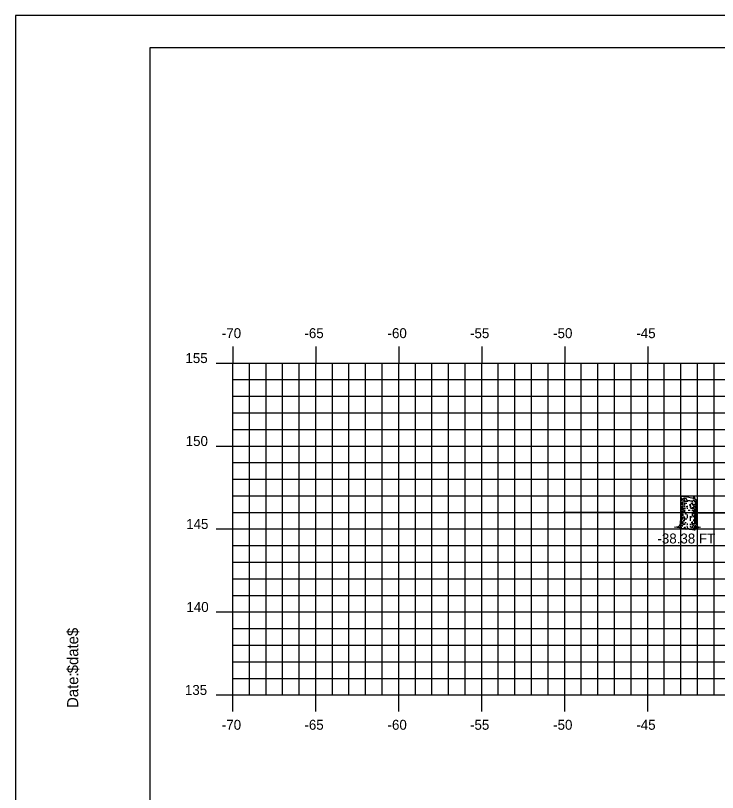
# Model space of a CAD drawing. Extents: x 1146746 to 1146916, y 608981 to 609091.
# Drawn here: x 1146746.33 to 1146788.63, y 609044.46 to 609091.28 of the extents above; entities that cross this region are included whole.
import ezdxf

# ---------------------------------------------------------------- set-up
doc = ezdxf.new("R2010")
doc.units = 0
for name, color, linetype in [('BORDER', 7, 'Continuous'), ('D_Text_Standard', 7, 'Continuous'), ('H_V ANNOTATION', 7, 'Continuous'), ('MAJOR', 7, 'Continuous'), ('MINOR', 7, 'Continuous'), ('PLOT BOUNDARY', 7, 'Continuous'), ('S_Roadway_Centerline', 7, 'Continuous'), ('S_Trees_Decid_NonPay', 7, 'Continuous')]:
    doc.layers.add(name, color=color, linetype=linetype)

msp = doc.modelspace()

# ---------------------------------------------------------------- linework, layer by layer
at = {"layer": 'BORDER'}
msp.add_lwpolyline([(1146754.428, 608984.335), (1146914.428, 608984.335), (1146914.428, 609089.335), (1146754.428, 609089.335)], close=True, dxfattribs=at)
at = {"layer": 'MAJOR'}
for p, q in [((1146759.428, 609071.337), (1146759.428, 609070.335)), ((1146764.428, 609071.337), (1146764.428, 609070.335)), ((1146769.428, 609071.337), (1146769.428, 609070.335)), ((1146774.428, 609071.337), (1146774.428, 609070.335)), ((1146779.428, 609071.337), (1146779.428, 609070.335)), ((1146784.428, 609071.337), (1146784.428, 609070.335)), ((1146758.426, 609070.335), (1146759.428, 609070.335)), ((1146759.428, 609070.335), (1146899.428, 609070.335)), ((1146759.428, 609050.335), (1146759.428, 609070.335)), ((1146759.428, 609050.335), (1146759.428, 609070.335)), ((1146759.428, 609070.335), (1146899.428, 609070.335)), ((1146764.428, 609050.335), (1146764.428, 609070.335)), ((1146769.428, 609050.335), (1146769.428, 609070.335)), ((1146774.428, 609050.335), (1146774.428, 609070.335)), ((1146779.428, 609050.335), (1146779.428, 609070.335)), ((1146784.428, 609050.335), (1146784.428, 609070.335)), ((1146758.426, 609065.335), (1146759.428, 609065.335)), ((1146759.428, 609065.335), (1146899.428, 609065.335)), ((1146758.426, 609060.335), (1146759.428, 609060.335)), ((1146759.428, 609060.335), (1146899.428, 609060.335)), ((1146758.426, 609055.335), (1146759.428, 609055.335)), ((1146759.428, 609055.335), (1146899.428, 609055.335)), ((1146758.426, 609050.335), (1146759.428, 609050.335)), ((1146759.428, 609050.335), (1146899.428, 609050.335)), ((1146759.428, 609050.335), (1146899.428, 609050.335)), ((1146759.428, 609049.333), (1146759.428, 609050.335)), ((1146764.428, 609049.333), (1146764.428, 609050.335)), ((1146769.428, 609049.333), (1146769.428, 609050.335)), ((1146774.428, 609049.333), (1146774.428, 609050.335)), ((1146779.428, 609049.333), (1146779.428, 609050.335)), ((1146784.428, 609049.333), (1146784.428, 609050.335))]:
    msp.add_line(p, q, dxfattribs=at)
at = {"layer": 'MINOR'}
for p, q in [((1146760.428, 609050.335), (1146760.428, 609070.335)), ((1146761.428, 609050.335), (1146761.428, 609070.335)), ((1146762.428, 609050.335), (1146762.428, 609070.335)), ((1146763.428, 609050.335), (1146763.428, 609070.335)), ((1146765.428, 609050.335), (1146765.428, 609070.335)), ((1146766.428, 609050.335), (1146766.428, 609070.335)), ((1146767.428, 609050.335), (1146767.428, 609070.335)), ((1146768.428, 609050.335), (1146768.428, 609070.335)), ((1146770.428, 609050.335), (1146770.428, 609070.335)), ((1146771.428, 609050.335), (1146771.428, 609070.335)), ((1146772.428, 609050.335), (1146772.428, 609070.335)), ((1146773.428, 609050.335), (1146773.428, 609070.335)), ((1146775.428, 609050.335), (1146775.428, 609070.335)), ((1146776.428, 609050.335), (1146776.428, 609070.335)), ((1146777.428, 609050.335), (1146777.428, 609070.335)), ((1146778.428, 609050.335), (1146778.428, 609070.335)), ((1146780.428, 609050.335), (1146780.428, 609070.335)), ((1146781.428, 609050.335), (1146781.428, 609070.335)), ((1146782.428, 609050.335), (1146782.428, 609070.335)), ((1146783.428, 609050.335), (1146783.428, 609070.335)), ((1146785.428, 609050.335), (1146785.428, 609070.335)), ((1146786.428, 609050.335), (1146786.428, 609070.335)), ((1146787.428, 609050.335), (1146787.428, 609070.335)), ((1146788.428, 609050.335), (1146788.428, 609070.335)), ((1146759.428, 609069.335), (1146899.428, 609069.335)), ((1146759.428, 609069.335), (1146760.43, 609069.335)), ((1146759.428, 609068.335), (1146899.428, 609068.335)), ((1146759.428, 609068.335), (1146760.43, 609068.335)), ((1146759.428, 609067.335), (1146899.428, 609067.335)), ((1146759.428, 609067.335), (1146760.43, 609067.335)), ((1146759.428, 609066.335), (1146899.428, 609066.335)), ((1146759.428, 609066.335), (1146760.43, 609066.335)), ((1146759.428, 609064.335), (1146899.428, 609064.335)), ((1146759.428, 609064.335), (1146760.43, 609064.335)), ((1146759.428, 609063.335), (1146899.428, 609063.335)), ((1146759.428, 609063.335), (1146760.43, 609063.335)), ((1146759.428, 609062.335), (1146899.428, 609062.335)), ((1146759.428, 609062.335), (1146760.43, 609062.335)), ((1146759.428, 609061.335), (1146899.428, 609061.335)), ((1146759.428, 609061.335), (1146760.43, 609061.335)), ((1146759.428, 609059.335), (1146899.428, 609059.335)), ((1146759.428, 609059.335), (1146760.43, 609059.335)), ((1146759.428, 609058.335), (1146899.428, 609058.335)), ((1146759.428, 609058.335), (1146760.43, 609058.335)), ((1146759.428, 609057.335), (1146899.428, 609057.335)), ((1146759.428, 609057.335), (1146760.43, 609057.335)), ((1146759.428, 609056.335), (1146899.428, 609056.335)), ((1146759.428, 609056.335), (1146760.43, 609056.335)), ((1146759.428, 609054.335), (1146899.428, 609054.335)), ((1146759.428, 609054.335), (1146760.43, 609054.335)), ((1146759.428, 609053.335), (1146899.428, 609053.335)), ((1146759.428, 609053.335), (1146760.43, 609053.335)), ((1146759.428, 609052.335), (1146899.428, 609052.335)), ((1146759.428, 609052.335), (1146760.43, 609052.335)), ((1146759.428, 609051.335), (1146899.428, 609051.335)), ((1146759.428, 609051.335), (1146760.43, 609051.335))]:
    msp.add_line(p, q, dxfattribs=at)
at = {"layer": 'PLOT BOUNDARY'}
msp.add_lwpolyline([(1146746.335, 608981.276), (1146916.335, 608981.276), (1146916.335, 609091.276), (1146746.335, 609091.276)], close=True, dxfattribs=at)
at = {"layer": 'S_Roadway_Centerline'}
msp.add_lwpolyline([(1146779.336, 609061.362), (1146783.547, 609061.347), (1146805.256, 609061.134), (1146809.082, 609059.861), (1146811.069, 609059.254), (1146812.495, 609059.513), (1146815.447, 609060.131), (1146817.252, 609060.222), (1146817.72, 609060.231), (1146827.705, 609060.397), (1146828.534, 609060.409), (1146838.673, 609060.265), (1146839.449, 609060.245), (1146840.103, 609060.192), (1146841.398, 609060.074), (1146844.953, 609059.719), (1146845.827, 609059.059), (1146847.055, 609058.398), (1146848.196, 609058.671), (1146848.525, 609058.74), (1146851.732, 609059.665), (1146855.862, 609060.73), (1146861.215, 609060.999), (1146871.652, 609060.902)], dxfattribs=at)
at = {"layer": 'S_Trees_Decid_NonPay'}
for p, q in [((1146786.469, 609062.189), (1146786.469, 609062.095)), ((1146786.469, 609061.868), (1146786.469, 609061.786)), ((1146786.537, 609062.103), (1146786.537, 609061.802)), ((1146786.537, 609061.773), (1146786.537, 609061.642)), ((1146786.656, 609062.12), (1146786.656, 609061.971)), ((1146786.656, 609061.923), (1146786.656, 609061.755)), ((1146786.803, 609062.074), (1146786.803, 609061.967)), ((1146786.803, 609061.738), (1146786.803, 609061.652)), ((1146786.983, 609061.838), (1146786.983, 609061.637)), ((1146787.1, 609062.021), (1146787.1, 609061.943)), ((1146787.1, 609061.856), (1146787.1, 609061.771)), ((1146787.187, 609061.838), (1146787.187, 609061.751)), ((1146787.258, 609062.011), (1146787.258, 609061.959)), ((1146787.258, 609061.856), (1146787.258, 609061.773)), ((1146787.258, 609061.738), (1146787.258, 609061.664)), ((1146787.3, 609062.016), (1146787.3, 609061.798)), ((1146787.3, 609061.729), (1146787.3, 609061.578)), ((1146787.327, 609061.946), (1146787.327, 609061.864)), ((1146787.327, 609061.794), (1146787.327, 609061.664)), ((1146786.469, 609061.716), (1146786.469, 609061.465)), ((1146786.469, 609061.382), (1146786.469, 609061.152)), ((1146786.537, 609061.608), (1146786.537, 609061.327)), ((1146786.537, 609061.257), (1146786.537, 609061.112)), ((1146786.656, 609061.448), (1146786.656, 609061.3)), ((1146786.803, 609061.617), (1146786.803, 609061.547)), ((1146787.1, 609061.66), (1146787.1, 609061.559)), ((1146787.1, 609061.475), (1146787.1, 609061.399)), ((1146787.187, 609061.681), (1146787.187, 609061.559)), ((1146787.187, 609061.484), (1146787.187, 609061.37)), ((1146787.187, 609061.308), (1146787.187, 609061.226)), ((1146787.258, 609061.637), (1146787.258, 609061.578)), ((1146787.258, 609061.525), (1146787.258, 609061.343)), ((1146787.258, 609061.312), (1146787.258, 609061.23)), ((1146787.3, 609061.473), (1146787.3, 609061.395)), ((1146787.3, 609061.368), (1146787.3, 609061.261)), ((1146787.327, 609061.642), (1146787.327, 609061.46)), ((1146787.327, 609061.413), (1146787.327, 609061.166)), ((1146786.469, 609061.082), (1146786.469, 609060.921)), ((1146786.469, 609060.904), (1146786.469, 609060.799)), ((1146786.537, 609061.042), (1146786.537, 609060.901)), ((1146786.537, 609060.799), (1146786.537, 609060.618)), ((1146786.656, 609061.03), (1146786.656, 609060.878)), ((1146786.803, 609061.214), (1146786.803, 609060.991)), ((1146786.983, 609061.1), (1146786.983, 609060.913)), ((1146786.983, 609060.882), (1146786.983, 609060.829)), ((1146787.1, 609061.214), (1146787.1, 609061.116)), ((1146787.1, 609060.792), (1146787.1, 609060.567)), ((1146787.187, 609061.139), (1146787.187, 609061.042)), ((1146787.187, 609060.913), (1146787.187, 609060.814)), ((1146787.258, 609061.176), (1146787.258, 609061.006)), ((1146787.258, 609060.972), (1146787.258, 609060.693)), ((1146787.3, 609061.226), (1146787.3, 609061.125)), ((1146787.3, 609061.099), (1146787.3, 609060.917)), ((1146787.3, 609060.814), (1146787.3, 609060.622)), ((1146787.327, 609061.147), (1146787.327, 609061.053)), ((1146787.329, 609061), (1146787.328, 609060.74)), ((1146786.469, 609060.763), (1146786.469, 609060.639)), ((1146786.536, 609060.559), (1146786.495, 609060.462)), ((1146786.656, 609060.666), (1146786.656, 609060.588)), ((1146786.803, 609060.658), (1146786.803, 609060.591)), ((1146786.843, 609060.372), (1146786.808, 609060.517)), ((1146786.983, 609060.653), (1146786.983, 609060.563)), ((1146787.187, 609060.685), (1146787.187, 609060.626)), ((1146787.258, 609060.64), (1146787.258, 609060.614)), ((1146787.298, 609060.575), (1146787.333, 609060.524)), ((1146787.38, 609060.454), (1146787.313, 609060.485)), ((1146787.327, 609060.701), (1146787.327, 609060.627))]:
    msp.add_line(p, q, dxfattribs=at)
for points in [[(1146787.368, 609062.053), (1146787.368, 609060.641), (1146787.391, 609060.493), (1146787.594, 609060.45), (1146787.454, 609060.414), (1146787.236, 609060.396), (1146787.166, 609060.353), (1146787.288, 609060.264), (1146786.956, 609060.307), (1146786.843, 609060.372), (1146786.75, 609060.311), (1146786.695, 609060.39), (1146786.703, 609060.427), (1146786.641, 609060.429), (1146786.59, 609060.372), (1146786.357, 609060.32), (1146786.485, 609060.408), (1146786.353, 609060.41), (1146786.044, 609060.448), (1146786.283, 609060.479), (1146786.361, 609060.536), (1146786.4, 609060.658), (1146786.417, 609061.011), (1146786.417, 609062.245)], [(1146786.781, 609062.079), (1146786.773, 609062.146), (1146786.748, 609062.151), (1146786.74, 609062.185), (1146786.709, 609062.171), (1146786.695, 609062.185), (1146786.67, 609062.162), (1146786.647, 609062.171), (1146786.635, 609062.22), (1146786.627, 609062.177), (1146786.596, 609062.185), (1146786.593, 609062.134)], [(1146787.273, 609062.134), (1146787.269, 609062.229), (1146787.255, 609062.202), (1146787.255, 609062.323), (1146787.234, 609062.259), (1146787.22, 609062.292), (1146787.203, 609062.236), (1146787.187, 609062.254), (1146787.168, 609062.245), (1146787.149, 609062.178)], [(1146787.251, 609062.01), (1146787.234, 609062.072), (1146787.212, 609062.06), (1146787.181, 609062.095), (1146787.147, 609062.017)], [(1146786.466, 609060.596), (1146786.458, 609060.519), (1146786.38, 609060.47)], [(1146786.991, 609060.513), (1146786.991, 609060.477), (1146787.042, 609060.446), (1146787.059, 609060.396)], [(1146787.103, 609060.519), (1146787.109, 609060.45), (1146787.172, 609060.437)], [(1146787.25, 609060.485), (1146787.207, 609060.519), (1146787.199, 609060.567)], [(1146787.329, 609060.501), (1146787.25, 609060.485), (1146787.234, 609060.441)]]:
    msp.add_lwpolyline(points, dxfattribs=at)
for centre, radius, start, end in [((1146786.435, 609062.245), 0.0179, 168.1723, 184.2278), ((1146786.441, 609062.246), 0.0237, 184.2278, 198.1723), ((1146786.435, 609062.245), 0.0179, 152.1168, 168.1723), ((1146786.45, 609062.249), 0.0336, 198.1723, 216.9486), ((1146786.44, 609062.242), 0.0237, 138.1723, 152.1168), ((1146786.448, 609062.236), 0.0336, 119.396, 138.1723), ((1146786.498, 609062.285), 0.0935, 216.9486, 228.1723), ((1146786.477, 609062.184), 0.0935, 108.1723, 119.396), ((1146786.651, 609062.455), 0.322, 228.1723, 250.2902), ((1146786.548, 609061.967), 0.322, 86.0543, 108.1723), ((1146786.398, 609059.787), 2.507, 78.1723, 86.0543), ((1146786.398, 609059.787), 2.507, 70.2902, 78.1723), ((1146786.436, 609062.098), 0.0191, 163.9485, 180), ((1146786.436, 609062.098), 0.0191, 180, 196.0515), ((1146786.442, 609062.099), 0.0252, 196.0515, 210), ((1146786.436, 609061.884), 0.0191, 163.9485, 180), ((1146786.436, 609061.884), 0.0191, 180, 196.0515), ((1146786.442, 609061.885), 0.0252, 196.0515, 210), ((1146786.436, 609061.781), 0.0191, 163.9485, 180), ((1146786.436, 609061.781), 0.0191, 180, 196.0515), ((1146786.442, 609061.782), 0.0252, 196.0515, 210), ((1146786.451, 609062.105), 0.0356, 210, 228.7494), ((1146786.451, 609061.89), 0.0356, 210, 228.7494), ((1146786.451, 609061.788), 0.0356, 210, 228.7494), ((1146786.492, 609062.152), 0.0984, 228.7494, 240), ((1146786.492, 609061.938), 0.0984, 228.7494, 240), ((1146786.492, 609061.835), 0.0984, 228.7494, 240), ((1146786.606, 609062.349), 0.326, 240, 248.3243), ((1146786.606, 609062.135), 0.326, 240, 243.5719), ((1146786.606, 609062.032), 0.326, 240, 243.243), ((1146786.606, 609062.236), 0.326, 240.9099, 257.8036), ((1146786.606, 609062.135), 0.326, 250.4167, 261.8968), ((1146786.606, 609062.349), 0.326, 257.8036, 261.8968), ((1146787.388, 609064.512), 2.507, 250.2902, 251.5281), ((1146786.892, 609064.359), 2.356, 261.8968, 263.2799), ((1146786.892, 609064.145), 2.356, 261.8968, 262.5519), ((1146786.892, 609064.246), 2.356, 264.242, 267.3673), ((1146786.892, 609064.359), 2.356, 265.24, 267.8386), ((1146787.388, 609064.512), 2.507, 255.9987, 258.1723), ((1146787.388, 609064.512), 2.507, 258.1723, 264.5013), ((1146786.892, 609064.145), 2.356, 270.8119, 272.1981), ((1146786.892, 609064.246), 2.356, 273.1481, 276.7734), ((1146786.892, 609064.145), 2.356, 275.0647, 278.1032), ((1146787.178, 609062.135), 0.326, 278.1032, 279.0854), ((1146787.135, 609061.844), 0.322, 48.1723, 70.2902), ((1146787.237, 609062.332), 0.322, 272.4479, 288.1723), ((1146787.178, 609062.236), 0.326, 291.9506, 300), ((1146787.178, 609062.135), 0.326, 291.9506, 300), ((1146787.308, 609062.115), 0.0935, 288.1723, 299.396), ((1146787.292, 609062.039), 0.0984, 300, 311.2506), ((1146787.292, 609061.938), 0.0984, 300, 311.2506), ((1146787.287, 609062.014), 0.0935, 36.9486, 48.1723), ((1146787.338, 609062.063), 0.0336, 299.396, 318.1723), ((1146787.333, 609061.991), 0.0356, 311.2506, 330), ((1146787.333, 609061.89), 0.0356, 311.2506, 330), ((1146787.335, 609062.05), 0.0336, 18.1723, 36.9486), ((1146787.345, 609062.056), 0.0237, 318.1723, 332.1168), ((1146787.342, 609061.986), 0.0252, 330, 343.9485), ((1146787.342, 609061.885), 0.0252, 330, 343.9485), ((1146787.35, 609062.053), 0.0179, 332.1168, 348.1723), ((1146787.344, 609062.053), 0.0237, 4.2278, 18.1723), ((1146787.348, 609061.984), 0.0191, 360, 6.1128), ((1146787.348, 609061.984), 0.0191, 343.9485, 360), ((1146787.348, 609061.884), 0.0191, 360, 6.1128), ((1146787.348, 609061.884), 0.0191, 343.9485, 360), ((1146787.348, 609061.781), 0.0191, 360, 6.1128), ((1146787.348, 609061.781), 0.0191, 343.9485, 360), ((1146787.35, 609062.053), 0.0179, 348.1723, 4.2278), ((1146786.433, 609061.346), 0.0191, 163.9485, 180), ((1146786.436, 609061.561), 0.0191, 163.9485, 180), ((1146786.436, 609061.561), 0.0191, 180, 196.0515), ((1146786.442, 609061.562), 0.0252, 196.0515, 210), ((1146786.436, 609061.446), 0.0191, 163.9485, 180), ((1146786.436, 609061.446), 0.0191, 180, 196.0515), ((1146786.442, 609061.448), 0.0252, 196.0515, 210), ((1146786.451, 609061.567), 0.0356, 210, 228.7494), ((1146786.451, 609061.453), 0.0356, 210, 228.7494), ((1146786.492, 609061.615), 0.0984, 228.7494, 240), ((1146786.493, 609061.5), 0.0984, 228.7494, 240), ((1146786.603, 609061.597), 0.326, 240, 256.9079), ((1146786.606, 609061.812), 0.326, 240, 245.1545), ((1146786.607, 609061.697), 0.326, 240, 247.8656), ((1146786.606, 609061.927), 0.326, 245.1545, 257.8036), ((1146786.606, 609062.032), 0.326, 251.6831, 257.8036), ((1146786.607, 609061.697), 0.326, 257.6699, 261.8968), ((1146786.893, 609063.707), 2.356, 261.8968, 262.8615), ((1146786.892, 609063.822), 2.356, 262.6588, 264.7911), ((1146786.892, 609063.937), 2.356, 263.2682, 265.6362), ((1146786.892, 609064.042), 2.356, 263.3413, 264.9946), ((1146786.89, 609063.607), 2.356, 264.3443, 266.8529), ((1146786.892, 609064.042), 2.356, 266.5036, 267.8386), ((1146786.892, 609063.822), 2.356, 269.5578, 270), ((1146786.892, 609063.822), 2.356, 270, 272.414), ((1146786.892, 609064.042), 2.356, 272.1981, 273.9741), ((1146786.892, 609063.937), 2.356, 273.0067, 275.0647), ((1146786.89, 609063.607), 2.356, 274.9734, 277.2455), ((1146786.892, 609063.822), 2.356, 275.0647, 277.1868), ((1146786.892, 609063.937), 2.356, 277.1868, 278.1032), ((1146786.892, 609064.042), 2.356, 277.3838, 278.1032), ((1146787.178, 609062.032), 0.326, 278.1032, 284.0382), ((1146787.178, 609061.927), 0.326, 278.1032, 284.0382), ((1146787.178, 609061.812), 0.326, 284.0382, 300), ((1146787.179, 609061.697), 0.326, 283.9036, 291.8098), ((1146787.178, 609061.927), 0.326, 291.9506, 300), ((1146787.176, 609061.597), 0.326, 292.4049, 300), ((1146787.179, 609061.697), 0.326, 297.0058, 300), ((1146787.29, 609061.4), 0.0984, 300, 311.2506), ((1146787.292, 609061.73), 0.0984, 300, 311.2506), ((1146787.292, 609061.615), 0.0984, 300, 311.2506), ((1146787.293, 609061.5), 0.0984, 300, 311.2506), ((1146787.331, 609061.353), 0.0356, 311.2506, 330), ((1146787.333, 609061.683), 0.0356, 311.2506, 330), ((1146787.333, 609061.567), 0.0356, 311.2506, 330), ((1146787.334, 609061.453), 0.0356, 311.2506, 330), ((1146787.34, 609061.348), 0.0252, 330, 343.9485), ((1146787.342, 609061.677), 0.0252, 330, 343.9485), ((1146787.342, 609061.562), 0.0252, 330, 343.9485), ((1146787.346, 609061.346), 0.0191, 343.9485, 360), ((1146787.343, 609061.448), 0.0252, 330, 343.9485), ((1146787.346, 609061.346), 0.0191, 0, 6.1128), ((1146787.348, 609061.676), 0.0191, 360, 6.1128), ((1146787.348, 609061.676), 0.0191, 343.9485, 360), ((1146787.348, 609061.561), 0.0191, 360, 6.1128), ((1146787.348, 609061.561), 0.0191, 343.9485, 360), ((1146787.349, 609061.446), 0.0191, 343.9485, 360), ((1146787.349, 609061.446), 0.0191, 0, 6.1128), ((1146786.427, 609060.811), 0.0191, 163.9485, 180), ((1146786.427, 609060.811), 0.0191, 180, 196.0515), ((1146786.433, 609060.813), 0.0252, 196.0515, 210), ((1146786.442, 609060.818), 0.0356, 210, 228.7494), ((1146786.432, 609060.922), 0.0191, 163.9485, 180), ((1146786.432, 609060.922), 0.0191, 180, 196.0515), ((1146786.437, 609060.924), 0.0252, 196.0515, 210), ((1146786.447, 609060.929), 0.0356, 210, 228.7494), ((1146786.436, 609061.241), 0.0191, 163.9485, 180), ((1146786.436, 609061.241), 0.0191, 180, 196.0515), ((1146786.442, 609061.243), 0.0252, 196.0515, 210), ((1146786.483, 609060.866), 0.0984, 228.7494, 240), ((1146786.451, 609061.248), 0.0356, 210, 228.7494), ((1146786.488, 609060.976), 0.0984, 228.7494, 240), ((1146786.492, 609061.295), 0.0984, 228.7494, 240), ((1146786.602, 609061.173), 0.326, 240, 245.9375), ((1146786.606, 609061.492), 0.326, 240, 245.1545), ((1146786.606, 609061.402), 0.326, 241.939, 253.9183), ((1146786.888, 609063.183), 2.356, 262.2226, 264.4852), ((1146786.892, 609063.412), 2.356, 262.5843, 264.4865), ((1146786.892, 609063.299), 2.356, 264.242, 267.469), ((1146786.892, 609063.502), 2.356, 267.8386, 269.0054), ((1146786.892, 609063.412), 2.356, 272.1981, 275.2726), ((1146786.892, 609063.502), 2.356, 275.0647, 276.428), ((1146786.888, 609063.183), 2.356, 277.2863, 278.1032), ((1146787.174, 609061.173), 0.326, 278.1032, 284.7741), ((1146787.178, 609061.492), 0.326, 284.0382, 291.9506), ((1146787.178, 609061.289), 0.326, 284.0382, 291.9506), ((1146787.178, 609061.492), 0.326, 297.1525, 300), ((1146787.288, 609060.976), 0.0984, 300, 311.2506), ((1146787.292, 609061.295), 0.0984, 300, 311.2506), ((1146787.329, 609060.929), 0.0356, 311.2506, 330), ((1146787.333, 609061.248), 0.0356, 311.2506, 330), ((1146787.338, 609060.924), 0.0252, 330, 343.9485), ((1146787.344, 609060.922), 0.0191, 360, 6.1128), ((1146787.344, 609060.922), 0.0191, 343.9485, 360), ((1146787.342, 609061.243), 0.0252, 330, 343.9485), ((1146787.348, 609061.241), 0.0191, 360, 6.1128), ((1146787.348, 609061.241), 0.0191, 343.9485, 360), ((1146787.348, 609061.151), 0.0191, 360, 6.1128), ((1146786.421, 609060.701), 0.0191, 163.9485, 180), ((1146786.421, 609060.701), 0.0191, 180, 196.0515), ((1146786.427, 609060.703), 0.0252, 196.0515, 210), ((1146786.436, 609060.708), 0.0356, 210, 228.7494), ((1146786.478, 609060.755), 0.0984, 228.7494, 240), ((1146786.591, 609060.953), 0.326, 240, 247.9161), ((1146786.597, 609061.063), 0.326, 240, 241.9097), ((1146786.591, 609060.953), 0.326, 260.3834, 261.8968), ((1146786.878, 609062.963), 2.356, 261.8968, 263.5333), ((1146786.883, 609063.073), 2.356, 264.9089, 266.8158), ((1146786.883, 609063.073), 2.356, 274.1864, 275.2829), ((1146786.878, 609062.963), 2.356, 274.5551, 275.4167), ((1146786.878, 609062.963), 2.356, 277.5403, 278.1032), ((1146787.164, 609060.953), 0.326, 278.1032, 294.7094), ((1146787.169, 609061.063), 0.326, 293.6544, 300), ((1146787.278, 609060.755), 0.0984, 300, 311.2506), ((1146787.319, 609060.708), 0.0356, 311.2506, 330), ((1146787.328, 609060.703), 0.0252, 330, 343.9485), ((1146787.334, 609060.701), 0.0191, 343.9485, 360), ((1146787.334, 609060.701), 0.0191, 0, 6.1128)]:
    msp.add_arc(centre, radius, start, end, dxfattribs=at)

# ---------------------------------------------------------------- texts
at = {"layer": 'BORDER'}
for s, p in [('$date$', (1146750.113, 609051.64)), ('Date:', (1146750.113, 609049.552))]:
    msp.add_text(s, height=0.6696, rotation=90, dxfattribs=at).set_placement(p)
at = {"layer": 'D_Text_Standard'}
msp.add_text('-38.38 FT', height=0.6, dxfattribs=at).set_placement((1146785.017, 609059.462))
at = {"layer": 'H_V ANNOTATION'}
for s, p in [('-70', (1146758.769, 609071.835)), ('-65', (1146763.745, 609071.835)), ('-60', (1146768.753, 609071.835)), ('-55', (1146773.724, 609071.835)), ('-50', (1146778.732, 609071.835)), ('-45', (1146783.745, 609071.835)), ('155', (1146756.574, 609070.335)), ('150', (1146756.59, 609065.335)), ('145', (1146756.617, 609060.335)), ('140', (1146756.633, 609055.335)), ('135', (1146756.542, 609050.335)), ('-70', (1146758.769, 609048.235)), ('-65', (1146763.745, 609048.235)), ('-60', (1146768.753, 609048.235)), ('-55', (1146773.724, 609048.235)), ('-50', (1146778.732, 609048.235)), ('-45', (1146783.745, 609048.235))]:
    msp.add_text(s, height=0.6, dxfattribs=at).set_placement(p)
at = {"layer": 'MAJOR'}
msp.add_text('-', height=0.006, dxfattribs=at).set_placement((1146759.423, 609050.335))

doc.saveas('drawing.dxf')
